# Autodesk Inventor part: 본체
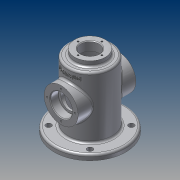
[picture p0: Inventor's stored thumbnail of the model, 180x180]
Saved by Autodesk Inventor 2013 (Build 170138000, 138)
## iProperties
Created: 2014-12
Part Number: 본체
Material: 알루미늄 6061
Document SubType Name: Modeling
Designer: HS002
Density: 2.71 g/cm^3
Mass: 479.567 g
Surface Area: 607.432 cm^2
Volume: 176.962 cm^3
Author: HS002
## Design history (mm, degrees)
sketch "스케치1"
  geometry: C1 r 32.5 at (0, 0); 1 further point
  constraints: 1 centre point, 1 coincident
  dimensions: "d0" = 65 diameter of C1
extrude "돌출1" new body sketch "스케치1" distance "d1" = 98; taper "d2" = 0 deg
fillet "모깎기1" dims "d3" = 3
feature "쉘1" dims "d4" = 5
fillet "모깎기2" dims "d5" = 3
sketch "스케치2"
  geometry: C1 r 29.5 at (0, 0) reference; C2 r 22.5 at (0, 0)
  constraints: 1 centre point, 1 coincident
  dimensions: "d6" = 45 diameter of C2
extrude "돌출2" join sketch "스케치2" distance "d7" = 8; taper "d8" = 0 deg
sketch "스케치3"
  geometry: C1 r 22.5 at (0, 0) reference; C2 r 13.5 at (0, 0)
  constraints: 1 centre point, 1 coincident
  dimensions: "d9" = 27 diameter of C2
extrude "돌출3" cut sketch "스케치3" distance "d10" = 111; taper "d11" = 0 deg
sketch "스케치4" dims "d12" = 35
  geometry: C1 r 22.5 at (0, 0) reference; C2 r 31.231 at (0, 17.5); 1 further point
  constraints: 1 centre point, 1 coincident, 1 vertical alignment, 2 other
hole "구멍1" sketch "스케치4" at (0, 17.5) diameter "d13" = 2.459; stored, may be unused: countersink angle "d17" = 90 deg, drill point angle "d19" = 118 deg; dims "d14" = 6, "d15" = 4, "d16" = 2, "d18" = 8
node "작업 평면1"
sketch "스케치5"
  geometry: C1 r 25 at (0, 55); 1 further point
  constraints: 1 centre point
  dimensions: "d24" = 50 diameter of C1; "d25" = 55 distance of C1.centre point (0, 0)
extrude "돌출4" join sketch "스케치5" stored distance "d26" = 111; taper "d27" = 0 deg
hole "구멍2" diameter "d30" = 25; stored, may be unused: countersink angle "d34" = 90 deg, drill point angle "d36" = 118 deg; dims "d28" = 10, "d29" = 10, "d31" = 6, "d32" = 32, "d33" = 12, "d35" = 42.5
sketch "스케치6" dims "d37" = 41
  geometry: C1 r 25 at (0, 0) reference; C2 r 9.403 at (-20.5, 0); 2 further points
  constraints: 1 centre point, 1 coincident, 1 horizontal alignment, 2 other
hole "구멍3" sketch "스케치6" at (-20.5, 0) diameter "d38" = 2.459; stored, may be unused: countersink angle "d42" = 90 deg, drill point angle "d44" = 118 deg; dims "d39" = 6, "d40" = 32, "d41" = 12, "d43" = 8
fillet "모깎기3" dims "d48" = 0.3
chamfer "모따기1" distance "d49" = 1; stored, may be unused: second distance "d50" = 2, angle "d51" = 45 deg
sketch "스케치7"
  geometry: C1 r 27.5 at (0, 0) reference; C2 r 32.5 at (0, 0) reference; C3 r 52.5 at (0, 0)
  constraints: 1 centre point, 1 coincident
  dimensions: "d52" = 105 diameter of C3
extrude "돌출5" join sketch "스케치7" distance "d53" = 8; taper "d54" = 0 deg
fillet "모깎기4" dims "d55" = 3
sketch "스케치8"
  geometry: L1 (0, 0)-(43, 0); L2 (0, 0)-(30.406, 30.406); C1 r 35.5 at (0, 0) reference; C2 r 4 at (30.406, 30.406); A1 r 43 centre (0, 0) between (43, 0) and (30.406, 30.406)
  constraints: 4 end point, 2 centre point, 2 coincident, 2 point on circle, 1 horizontal
  dimensions: "d56" = 86 diameter of A1; "d57" = 45 deg angle of L2 L1; "d59" = 8 diameter of C2
extrude "돌출6" cut sketch "스케치8" distance "d60" = 8; taper "d61" = 0 deg
node "작업 평면2"
sketch "스케치9"
  geometry: L1 (-29.5, 98)-(29.5, 98) reference; 3 further points
  constraints: 1 midpoint, 1 vertical alignment, 1 other
  dimensions: "d66" = 9 distance from line of L1 point (0, 89)
feature "엠보싱1" sketch "스케치9" dims "d67" = 1, "d68" = 0
node "솔리드1"
pattern_circular "원형 패턴1" dims angle "d21" = 360 deg
pattern_circular "원형 패턴2" dims angle "d46" = 360 deg
mirror "대칭1"
pattern_circular "원형 패턴3" dims angle "d63" = 360 deg
other parameters: "d23" = 42.5, "d65" = -32.5
